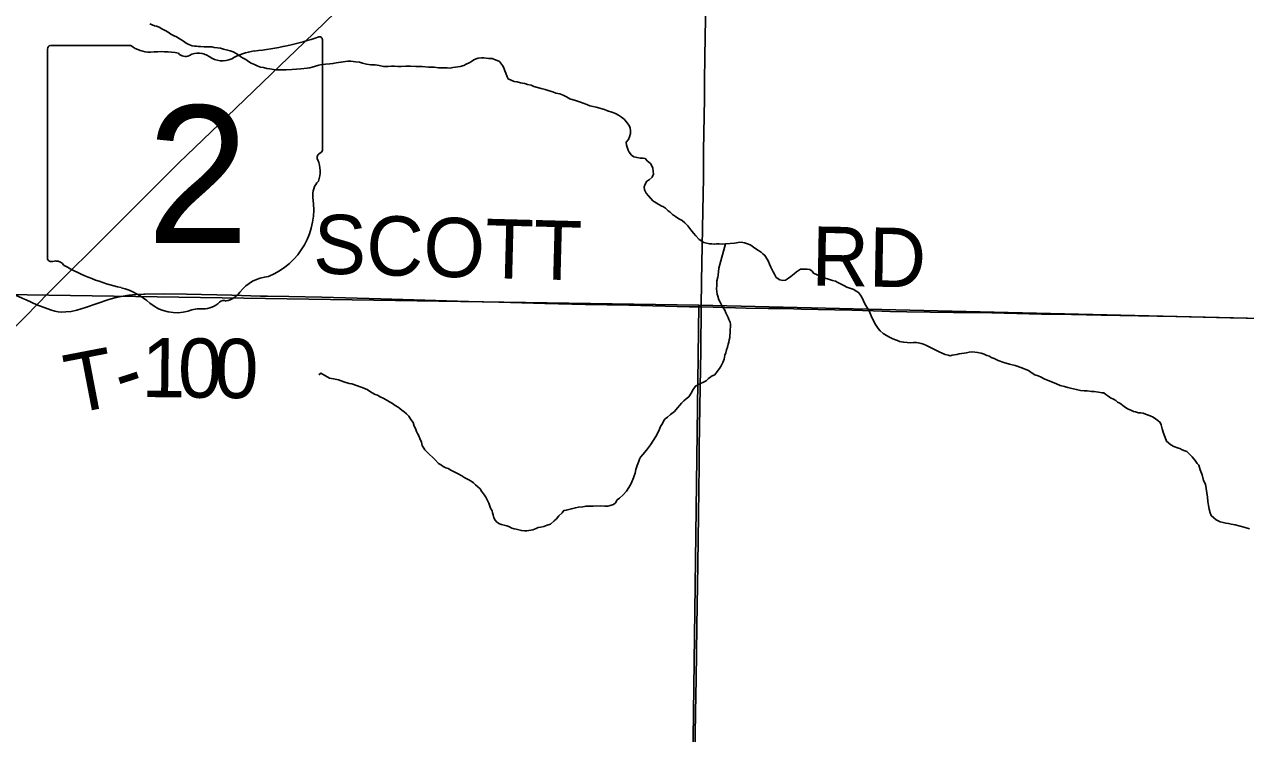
# Model space of a CAD drawing. Extents: x 0 to 34, y 0 to 22.
# Drawn here: x 3.972 to 5.144, y 15.073 to 15.753 of the extents above; entities that cross this region are included whole.
import ezdxf

# ---------------------------------------------------------------- set-up
doc = ezdxf.new("R2010")
doc.units = 0
for name, color, linetype in [('GM_X_County_Road', 7, 'Continuous'), ('GM_X_Minor_River', 7, 'Continuous'), ('GM_X_Section', 7, 'Continuous'), ('GM_X_State_Location', 7, 'Continuous'), ('GM_X_State_Route', 7, 'Continuous'), ('GM_X_State_Shield', 7, 'Continuous'), ('GM_X_Township_Road', 7, 'Continuous'), ('GM_X_Township_Road_Text', 7, 'Continuous')]:
    doc.layers.add(name, color=color, linetype=linetype)

msp = doc.modelspace()

# ---------------------------------------------------------------- linework, layer by layer
at = {"layer": 'GM_X_County_Road'}
for points in [[(3.6247, 15.4985), (3.6515, 15.4981), (3.6707, 15.4979), (3.7242, 15.4973), (3.7665, 15.4973), (3.8317, 15.4965), (3.8541, 15.4964), (3.8765, 15.4961), (3.9001, 15.4959), (3.9181, 15.4959), (3.9312, 15.4957), (3.9337, 15.4956), (3.9374, 15.4956), (3.9405, 15.4955), (3.9512, 15.4952), (3.9568, 15.4947), (3.9618, 15.4936), (3.966, 15.4922), (3.9709, 15.4899), (3.974, 15.4885), (3.9842, 15.4838)], [(3.9842, 15.4838), (3.9975, 15.4791), (4.0016, 15.4778), (4.0047, 15.4772), (4.0078, 15.4769), (4.0121, 15.477), (4.0171, 15.4775), (4.0225, 15.4787), (4.0308, 15.4813), (4.0532, 15.489), (4.0591, 15.4907), (4.0652, 15.492), (4.0726, 15.4932), (4.0794, 15.4939), (4.0868, 15.4942), (4.0878, 15.4942)], [(4.0878, 15.4942), (4.1055, 15.4943), (4.1279, 15.4941), (4.1714, 15.4931), (4.1987, 15.4923), (4.2055, 15.4921), (4.226, 15.4918), (4.2577, 15.4912), (4.3143, 15.4895), (4.346, 15.4886), (4.3982, 15.4871), (4.4274, 15.4865), (4.4715, 15.4852), (4.5107, 15.4842), (4.5523, 15.4835), (4.6101, 15.482), (4.6217, 15.4818)], [(4.6217, 15.4818), (4.6443, 15.4813), (4.6648, 15.4808), (4.6859, 15.4805), (4.7033, 15.4802), (4.7176, 15.4798), (4.7499, 15.4791), (4.7661, 15.4788), (4.7866, 15.4781), (4.8028, 15.4776), (4.8189, 15.4773), (4.8637, 15.4766), (4.9003, 15.4761), (4.9482, 15.475), (4.9768, 15.4745), (5.0054, 15.4739), (5.0769, 15.4726), (5.1291, 15.4714), (5.1595, 15.4708)]]:
    msp.add_lwpolyline(points, dxfattribs=at)
at = {"layer": 'GM_X_Minor_River'}
for points in [[(4.0926, 15.7531), (4.0949, 15.7523), (4.0971, 15.7514), (4.099, 15.751), (4.1017, 15.7502), (4.1043, 15.7486), (4.1073, 15.747), (4.1103, 15.7454), (4.1129, 15.7435), (4.1159, 15.7419), (4.1181, 15.7407), (4.1208, 15.7391), (4.1249, 15.7367), (4.1275, 15.7348), (4.1301, 15.7336), (4.1331, 15.7323), (4.1354, 15.7319), (4.1373, 15.7319), (4.1392, 15.7314), (4.1411, 15.7314), (4.1449, 15.7313), (4.1468, 15.7313), (4.1494, 15.7312), (4.1521, 15.7311), (4.1544, 15.7307), (4.1574, 15.7303), (4.1604, 15.7298), (4.1634, 15.729), (4.1672, 15.7281), (4.1698, 15.7273), (4.1725, 15.7265), (4.1755, 15.7249), (4.1781, 15.7233), (4.18, 15.7217), (4.1822, 15.7202), (4.1848, 15.719), (4.1874, 15.717), (4.1897, 15.7154), (4.1931, 15.7142), (4.1957, 15.713), (4.1987, 15.7118), (4.2017, 15.7114), (4.2048, 15.7105), (4.2078, 15.7101), (4.2112, 15.7096), (4.2138, 15.7092), (4.2169, 15.7091), (4.2199, 15.709), (4.2233, 15.7093), (4.229, 15.7096), (4.2332, 15.7099), (4.2374, 15.7101)], [(4.2374, 15.7101), (4.2435, 15.7107), (4.2461, 15.7111), (4.2484, 15.7118), (4.2549, 15.7135), (4.2576, 15.7142), (4.261, 15.7145), (4.2652, 15.7148), (4.2683, 15.7151), (4.2713, 15.7158), (4.2736, 15.7161), (4.2759, 15.7164), (4.2782, 15.7168), (4.2805, 15.7171), (4.2827, 15.7174), (4.2854, 15.7174), (4.2877, 15.7173), (4.2899, 15.7169), (4.2937, 15.7164), (4.2967, 15.7156), (4.3005, 15.7147), (4.3047, 15.7139), (4.3088, 15.7138), (4.3126, 15.7133), (4.3168, 15.7124), (4.321, 15.7123), (4.3244, 15.7126), (4.3274, 15.7126), (4.3305, 15.7125), (4.3339, 15.7124), (4.3381, 15.7127), (4.3426, 15.7126), (4.3479, 15.7125), (4.354, 15.7123), (4.3601, 15.7118), (4.3654, 15.7117), (4.3695, 15.7112), (4.3718, 15.7111), (4.3737, 15.7111), (4.3756, 15.711), (4.3779, 15.711), (4.3809, 15.7109), (4.3832, 15.7113), (4.3859, 15.7116), (4.3882, 15.7119), (4.3904, 15.7122), (4.3939, 15.7133), (4.3962, 15.7147), (4.3989, 15.7158), (4.4012, 15.7173), (4.4035, 15.7188), (4.4058, 15.7198), (4.4077, 15.7202), (4.4108, 15.7205), (4.413, 15.7208), (4.4176, 15.7199), (4.421, 15.7199), (4.4232, 15.719), (4.4259, 15.7182), (4.4281, 15.717), (4.4311, 15.7132), (4.4322, 15.7112), (4.4332, 15.7082), (4.4343, 15.7059), (4.4354, 15.7024), (4.4365, 15.7005), (4.4399, 15.6989), (4.4421, 15.6981), (4.4451, 15.6976), (4.4482, 15.6968), (4.45, 15.6964), (4.4523, 15.6959), (4.455, 15.6951), (4.4584, 15.6943), (4.461, 15.6931), (4.4644, 15.6922), (4.4682, 15.6914), (4.4719, 15.6902), (4.4757, 15.6889), (4.4791, 15.6881), (4.4821, 15.6869), (4.4859, 15.686), (4.4893, 15.6848), (4.4923, 15.6832), (4.4956, 15.6812), (4.5009, 15.6796), (4.5047, 15.6784), (4.5084, 15.6771), (4.5118, 15.6759), (4.5148, 15.6747), (4.5179, 15.6739), (4.5209, 15.6734), (4.5288, 15.671), (4.5318, 15.6697), (4.536, 15.6685), (4.5393, 15.6673), (4.5423, 15.6657), (4.545, 15.6637), (4.5476, 15.6618), (4.5494, 15.6598), (4.5516, 15.6571)], [(4.5516, 15.6571), (4.5527, 15.6552), (4.5534, 15.6533), (4.5538, 15.651), (4.5537, 15.648), (4.5529, 15.6449), (4.5517, 15.6423), (4.5497, 15.6397), (4.55, 15.637), (4.5504, 15.6351), (4.5514, 15.632), (4.5525, 15.6301), (4.5547, 15.6274), (4.557, 15.6258), (4.56, 15.625), (4.563, 15.6246), (4.5657, 15.6245), (4.5679, 15.6241), (4.5702, 15.6217), (4.5728, 15.6194), (4.5742, 15.6171), (4.5753, 15.6148), (4.5756, 15.6117), (4.5759, 15.609), (4.5747, 15.6064), (4.5716, 15.6038), (4.5693, 15.6024), (4.5677, 15.5997), (4.5669, 15.5971), (4.5672, 15.5941), (4.5687, 15.591), (4.5709, 15.5883), (4.5753, 15.5836), (4.5783, 15.5816), (4.581, 15.5801), (4.5832, 15.5789), (4.5855, 15.5777), (4.5873, 15.5765), (4.5899, 15.5741), (4.5918, 15.5726), (4.594, 15.5706), (4.597, 15.5687), (4.6, 15.5663), (4.6034, 15.5647), (4.606, 15.5624), (4.6086, 15.5596), (4.6115, 15.5558), (4.6141, 15.5527), (4.6163, 15.55), (4.6196, 15.5465), (4.6241, 15.5437), (4.6294, 15.5424), (4.6317, 15.5424), (4.6343, 15.5419), (4.6363, 15.5423), (4.6389, 15.5422), (4.6419, 15.5421), (4.645, 15.5424), (4.6534, 15.543), (4.6553, 15.5433), (4.6572, 15.5437), (4.6598, 15.544), (4.6632, 15.5432), (4.6651, 15.5427), (4.667, 15.5419), (4.6693, 15.5411), (4.6719, 15.5391), (4.6748, 15.5368), (4.679, 15.5344), (4.6808, 15.5329), (4.6827, 15.5313), (4.6849, 15.5278), (4.686, 15.5255), (4.6871, 15.5228), (4.6885, 15.5201), (4.6896, 15.5175), (4.6907, 15.5155), (4.6918, 15.5132), (4.6936, 15.5101), (4.6969, 15.5078), (4.7, 15.5073), (4.7026, 15.5076), (4.7053, 15.5095), (4.7077, 15.5109), (4.7108, 15.5135), (4.7131, 15.5154), (4.715, 15.5169), (4.7169, 15.5179), (4.7204, 15.5182), (4.723, 15.5182), (4.7257, 15.5177), (4.7279, 15.5162), (4.7294, 15.5142), (4.7327, 15.5126), (4.7357, 15.511), (4.7474, 15.5073), (4.7504, 15.5065), (4.7527, 15.5053), (4.7553, 15.5041), (4.7583, 15.5025), (4.7613, 15.5009)], [(4.645, 15.5424), (4.6384, 15.519), (4.6378, 15.5122), (4.6374, 15.5103), (4.6366, 15.5069), (4.6365, 15.5043), (4.6365, 15.5024), (4.6364, 15.4993), (4.6367, 15.4967), (4.637, 15.494), (4.6374, 15.4921), (4.6384, 15.4886), (4.6399, 15.4863), (4.641, 15.484), (4.6421, 15.4821), (4.6443, 15.4786), (4.6453, 15.4763), (4.6464, 15.4736), (4.6475, 15.4717), (4.6482, 15.4698), (4.6493, 15.4671), (4.6496, 15.4652), (4.6496, 15.4629), (4.6495, 15.4603), (4.6494, 15.4568), (4.649, 15.455), (4.649, 15.4527), (4.6485, 15.4504), (4.6481, 15.4481), (4.6473, 15.4463), (4.6468, 15.4432), (4.646, 15.4406), (4.6452, 15.4379), (4.6444, 15.4357), (4.644, 15.4338), (4.6435, 15.4319), (4.6423, 15.4285), (4.6407, 15.4255), (4.6391, 15.4229), (4.6368, 15.4199), (4.6345, 15.4169), (4.6321, 15.4158), (4.6287, 15.4133), (4.6263, 15.411), (4.6244, 15.4099), (4.6202, 15.4081), (4.6179, 15.4067), (4.616, 15.406), (4.614, 15.4026), (4.612, 15.3992), (4.6097, 15.3958), (4.607, 15.3936), (4.605, 15.3918), (4.6027, 15.3895), (4.6011, 15.3877), (4.5988, 15.3851), (4.596, 15.3817), (4.5922, 15.3788), (4.5891, 15.3762), (4.5871, 15.3747), (4.5856, 15.3729), (4.5844, 15.3702), (4.5824, 15.3672), (4.5808, 15.3631), (4.578, 15.3575), (4.5729, 15.3496), (4.569, 15.3444), (4.5655, 15.3403), (4.5635, 15.3377), (4.5623, 15.3358), (4.5615, 15.3331), (4.5603, 15.3298), (4.559, 15.326), (4.5582, 15.3226), (4.5574, 15.3199), (4.5566, 15.3181), (4.555, 15.3143), (4.5542, 15.312), (4.5522, 15.3087), (4.5498, 15.3053), (4.5467, 15.3016), (4.5432, 15.2986), (4.5409, 15.2968), (4.5393, 15.2941), (4.5374, 15.2923), (4.5343, 15.2916), (4.532, 15.2909), (4.529, 15.291), (4.5248, 15.2911), (4.518, 15.2909), (4.5134, 15.291), (4.5112, 15.291), (4.5081, 15.2903), (4.5039, 15.29), (4.5009, 15.2894), (4.497, 15.2883), (4.4921, 15.2869), (4.4898, 15.2866), (4.4882, 15.2843), (4.4851, 15.2817), (4.4828, 15.2788)], [(4.7613, 15.5009), (4.7643, 15.4997), (4.7681, 15.4985), (4.7703, 15.4969), (4.7726, 15.4957), (4.7744, 15.493), (4.7759, 15.4907), (4.7773, 15.4876), (4.7788, 15.4842), (4.781, 15.4807), (4.7824, 15.4784), (4.7832, 15.4765), (4.7846, 15.4734), (4.7857, 15.4711), (4.7868, 15.4688), (4.7882, 15.4661), (4.7893, 15.4642), (4.7915, 15.4611), (4.7934, 15.4588), (4.7963, 15.4564), (4.7993, 15.4544), (4.8023, 15.4529), (4.8053, 15.4513), (4.808, 15.4504), (4.8099, 15.4496), (4.8117, 15.4488), (4.8136, 15.4484), (4.8159, 15.448), (4.8193, 15.4479), (4.8227, 15.4474), (4.8254, 15.4477), (4.828, 15.4477), (4.8299, 15.4473), (4.8326, 15.4468), (4.8348, 15.446), (4.8378, 15.4448), (4.8408, 15.4432), (4.8506, 15.4384), (4.8555, 15.4364), (4.8585, 15.4356), (4.8604, 15.4351), (4.8623, 15.4355), (4.8646, 15.4358), (4.8669, 15.4361), (4.8692, 15.4368), (4.8714, 15.4372), (4.8737, 15.4375), (4.876, 15.4378), (4.8787, 15.4385), (4.8817, 15.4388), (4.8867, 15.4383), (4.8901, 15.4375), (4.8931, 15.4367), (4.8957, 15.4354), (4.898, 15.4346), (4.8998, 15.4335), (4.9025, 15.4323), (4.9066, 15.4306), (4.9119, 15.4286), (4.9175, 15.427), (4.9228, 15.4257), (4.9292, 15.4236), (4.933, 15.422), (4.9356, 15.4208), (4.9382, 15.4189), (4.9416, 15.4169), (4.945, 15.4157), (4.9476, 15.4145), (4.9506, 15.4129), (4.9544, 15.4113), (4.9585, 15.4096), (4.9623, 15.408), (4.966, 15.4064), (4.9702, 15.4056), (4.9732, 15.4047), (4.9773, 15.4035), (4.9815, 15.4026), (4.9853, 15.4018), (4.9891, 15.4013), (4.9917, 15.4013), (4.9959, 15.4008), (4.9985, 15.4007), (5.0027, 15.4002), (5.0061, 15.3994), (5.008, 15.3994), (5.0098, 15.3978), (5.0117, 15.3966), (5.0143, 15.3946), (5.017, 15.3934), (5.0192, 15.3923), (5.0211, 15.3907), (5.0233, 15.3895), (5.0274, 15.3864), (5.0304, 15.384), (5.033, 15.3832), (5.0364, 15.3816), (5.0383, 15.3812), (5.041, 15.3803), (5.0432, 15.3803), (5.0455, 15.3799), (5.0478, 15.379)], [(4.4828, 15.2788), (4.4805, 15.2769), (4.477, 15.2736), (4.4739, 15.2725), (4.4705, 15.2715), (4.4678, 15.2708), (4.4651, 15.2704), (4.4632, 15.2693), (4.4601, 15.2683), (4.4563, 15.2676), (4.4544, 15.2673), (4.4521, 15.2673), (4.4491, 15.2674), (4.4465, 15.2682), (4.4442, 15.2687), (4.4423, 15.2691), (4.44, 15.2699), (4.4378, 15.2711), (4.4352, 15.2719), (4.4325, 15.2727), (4.4299, 15.2732), (4.428, 15.274), (4.4254, 15.2756), (4.4239, 15.2775), (4.4228, 15.2798), (4.4221, 15.2825), (4.4214, 15.2844), (4.4211, 15.2863), (4.4196, 15.289), (4.4189, 15.2909), (4.4178, 15.2936), (4.4167, 15.2963), (4.4149, 15.2994), (4.4138, 15.3013), (4.4109, 15.3052), (4.4094, 15.3075), (4.4072, 15.3094), (4.405, 15.3114), (4.4031, 15.3133), (4.4009, 15.3149), (4.3979, 15.3165), (4.3949, 15.3181), (4.3919, 15.32), (4.3885, 15.322), (4.384, 15.324), (4.3814, 15.3252), (4.3787, 15.3268), (4.3765, 15.3276), (4.3742, 15.3288), (4.3724, 15.33), (4.3697, 15.3316), (4.3668, 15.3351), (4.3582, 15.3433), (4.3564, 15.3448), (4.3538, 15.3491), (4.3531, 15.3521), (4.3517, 15.3556), (4.3506, 15.3583), (4.3495, 15.3606), (4.3484, 15.3625), (4.3474, 15.3652), (4.3463, 15.3675), (4.3452, 15.3709), (4.343, 15.374), (4.3412, 15.3771), (4.339, 15.3794), (4.3367, 15.3814), (4.3345, 15.383), (4.3326, 15.3845), (4.3308, 15.3857), (4.3281, 15.3873), (4.3255, 15.3892), (4.3225, 15.3908), (4.3195, 15.3928), (4.3165, 15.3944), (4.3135, 15.3956), (4.3109, 15.3972), (4.3087, 15.398), (4.306, 15.3996), (4.3042, 15.4004), (4.3012, 15.4027), (4.2955, 15.4048), (4.291, 15.4064), (4.2865, 15.408), (4.2838, 15.4085), (4.2789, 15.4101), (4.2737, 15.4118), (4.2688, 15.413), (4.265, 15.4135), (4.2567, 15.4182), (4.2548, 15.4168)], [(5.0478, 15.379), (5.0523, 15.3774), (5.0553, 15.3762), (5.0575, 15.3746), (5.0598, 15.3731), (5.062, 15.3711), (5.0627, 15.3688), (5.0637, 15.365), (5.0652, 15.3608), (5.0666, 15.3566), (5.068, 15.3531), (5.0721, 15.3496), (5.0751, 15.348), (5.0785, 15.3468), (5.0808, 15.346), (5.083, 15.3448), (5.0857, 15.3439), (5.0875, 15.3431), (5.0927, 15.3381), (5.0953, 15.3346), (5.0975, 15.3319), (5.099, 15.33), (5.1004, 15.3257), (5.1022, 15.3208), (5.1036, 15.3154), (5.1054, 15.3119), (5.1074, 15.2994), (5.1077, 15.2952), (5.1083, 15.2914), (5.109, 15.2879), (5.1097, 15.2845), (5.1108, 15.2818), (5.1134, 15.2795), (5.1156, 15.2779), (5.1194, 15.2759), (5.1224, 15.2751), (5.125, 15.2746), (5.1273, 15.2742), (5.1299, 15.2737), (5.1337, 15.2729), (5.1386, 15.2716), (5.1435, 15.2704), (5.1477, 15.2691)]]:
    msp.add_lwpolyline(points, dxfattribs=at)
at = {"layer": 'GM_X_Section'}
for points in [[(3.6214, 15.4988), (4.6192, 15.4834), (4.6062, 14.4821), (3.6059, 14.5003)], [(4.6192, 15.4834), (5.6179, 15.4598), (5.6049, 14.4601), (4.6062, 14.4821)]]:
    msp.add_lwpolyline(points, close=True, dxfattribs=at)
at = {"layer": 'GM_X_State_Route'}
msp.add_lwpolyline([(3.7429, 15.246), (3.7509, 15.2537), (3.7877, 15.2898), (3.8134, 15.315), (3.8756, 15.376), (3.9195, 15.4191), (3.9491, 15.4484), (3.9737, 15.4731), (3.9842, 15.4838), (3.9959, 15.4956), (4.0561, 15.5559), (4.1204, 15.62), (4.1667, 15.6643), (4.2178, 15.7134), (4.2407, 15.7353), (4.2706, 15.7643), (4.3579, 15.8501), (4.3975, 15.8888), (4.4388, 15.9293), (4.4431, 15.9336)], dxfattribs=at)
at = {"layer": 'GM_X_State_Shield'}
for p, q in [((4.2582, 15.6328), (4.2582, 15.7375)), ((3.9946, 15.7291), (3.9946, 15.529)), ((4.0744, 15.7325), (3.9972, 15.7325)), ((4.2582, 15.6328), (4.2582, 15.6328))]:
    msp.add_line(p, q, dxfattribs=at)
for centre, radius, start, end in [((4.1643, 16.0053), 0.2796, 275.8445, 288.9065), ((4.2553, 15.7379), 0.00294, 351.8621, 97.738), ((3.9976, 15.7295), 0.00305, 98.1301, 188.1301), ((4.0928, 15.7557), 0.0296, 231.6195, 271.1119), ((4.1026, 15.6202), 0.1064, 80.4867, 94.9883), ((4.1267, 15.7305), 0.00855, 219.7921, 297.1024), ((4.1393, 15.7074), 0.0178, 54.4667, 119.1411), ((4.1622, 15.7391), 0.0214, 233.8562, 294.8282), ((4.2, 15.6714), 0.0563, 97.3462, 120.7689), ((4.2576, 15.6251), 0.00454, 107.944, 210.337), ((4.2551, 15.6324), 0.00314, 289.6038, 7.7341), ((4.2287, 15.6119), 0.0273, 340.033, 23.6496), ((4.2688, 15.589), 0.0198, 136.8065, 186.9296), ((4.18, 15.5757), 0.0699, 292.3089, 8.9858), ((3.9976, 15.5285), 0.00308, 171.9584, 258.3066), ((3.9981, 15.549), 0.0235, 267.339, 280.6039), ((4.0029, 15.5174), 0.00848, 29.7484, 93.2717), ((4.11, 15.6972), 0.2019, 240.4129, 257.1985), ((4.2095, 15.4728), 0.0383, 94.4031, 142.5768), ((4.0498, 15.439), 0.0632, 47.1842, 75.836), ((4.1635, 15.482), 0.00601, 65.7517, 132.6484), ((4.1609, 15.5096), 0.0226, 282.8732, 323.2771), ((4.1181, 15.5164), 0.0401, 230.7004, 286.2918), ((4.1412, 15.4472), 0.0329, 85.6951, 111.2099), ((4.1442, 15.5014), 0.0214, 268.777, 315.5493)]:
    msp.add_arc(centre, radius, start, end, dxfattribs=at)
at = {"layer": 'GM_X_Township_Road'}
for points in [[(4.6217, 15.4818), (4.622, 15.5067), (4.6231, 15.5739), (4.6237, 15.6056), (4.6239, 15.6317), (4.6247, 15.6814), (4.6247, 15.6982), (4.6252, 15.7218), (4.6256, 15.7585), (4.6261, 15.7871), (4.6265, 15.8256), (4.627, 15.8611), (4.6276, 15.8959), (4.6283, 15.9319), (4.629, 15.9711), (4.6299, 16.0202), (4.6307, 16.0749), (4.6307, 16.0769)], [(3.9842, 15.4838), (3.9975, 15.4791), (4.0016, 15.4778), (4.0047, 15.4772), (4.0078, 15.4769), (4.0121, 15.477), (4.0171, 15.4775), (4.0225, 15.4787), (4.0308, 15.4813), (4.0532, 15.489), (4.0591, 15.4907), (4.0652, 15.492), (4.0726, 15.4932), (4.0794, 15.4939), (4.0868, 15.4942), (4.0878, 15.4942)], [(4.0878, 15.4942), (4.1055, 15.4943), (4.1279, 15.4941), (4.1714, 15.4931), (4.1987, 15.4923), (4.2055, 15.4921), (4.226, 15.4918), (4.2577, 15.4912), (4.3143, 15.4895), (4.346, 15.4886), (4.3982, 15.4871), (4.4274, 15.4865), (4.4715, 15.4852), (4.5107, 15.4842), (4.5523, 15.4835), (4.6101, 15.482), (4.6217, 15.4818)], [(4.6155, 15.0492), (4.6162, 15.0933), (4.6166, 15.125), (4.6173, 15.1754), (4.6182, 15.2351), (4.6189, 15.2823), (4.6194, 15.3066), (4.6195, 15.3296), (4.6196, 15.347), (4.6207, 15.4048), (4.6212, 15.4402), (4.6217, 15.4818)], [(4.6217, 15.4818), (4.6443, 15.4813), (4.6648, 15.4808), (4.6859, 15.4805), (4.7033, 15.4802), (4.7176, 15.4798), (4.7499, 15.4791), (4.7661, 15.4788), (4.7866, 15.4781), (4.8028, 15.4776), (4.8189, 15.4773), (4.8637, 15.4766), (4.9003, 15.4761), (4.9482, 15.475), (4.9768, 15.4745), (5.0054, 15.4739), (5.0769, 15.4726), (5.1291, 15.4714), (5.1595, 15.4708)]]:
    msp.add_lwpolyline(points, dxfattribs=at)

# ---------------------------------------------------------------- texts
at = {"layer": 'GM_X_State_Location'}
for s in ['s', 'r']:
    msp.add_text(s, height=0.000189, dxfattribs=at).set_placement((4.1234, 15.6157))
msp.add_text('2', height=0.000189, rotation=0, dxfattribs=at).set_placement((4.0949, 15.6019))
at = {"layer": 'GM_X_State_Shield'}
msp.add_text('2', height=0.1318, dxfattribs=at).set_placement((4.0898, 15.5431))
at = {"layer": 'GM_X_Township_Road_Text'}
for s, height, rotation, p in [('SCOTT', 0.05682, 358.4922, (4.2489, 15.514)), ('RD', 0.05682, 359.0102, (4.7271, 15.5023)), ('1', 0.0568, 359.3235, (4.0843, 15.3955)), ('0', 0.0568, 359.2975, (4.1193, 15.3951)), ('0', 0.0568, 359.306, (4.1543, 15.3947)), ('T', 0.0568, 10.8865, (4.0177, 15.3791)), ('-', 0.0568, 17.9599, (4.0669, 15.3891))]:
    msp.add_text(s, height=height, rotation=rotation, dxfattribs=at).set_placement(p)

doc.saveas('drawing.dxf')
